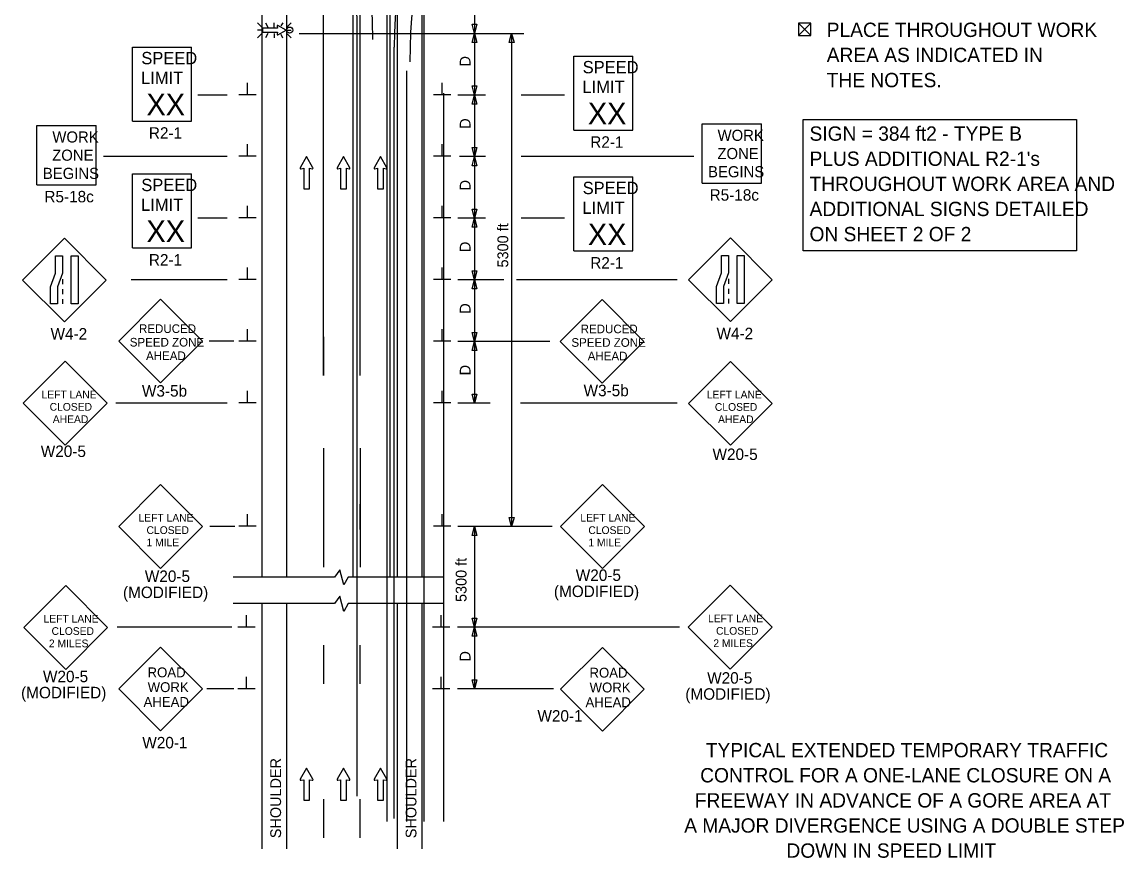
# Model space of a CAD drawing. Extents: x 16284 to 18474, y 5417 to 6974.
# Drawn here: x 16730 to 17445, y 5974 to 6516 of the extents above; entities that cross this region are included whole.
import ezdxf

# ---------------------------------------------------------------- set-up
doc = ezdxf.new("R2010")
doc.units = 0
for name, color, linetype in [('ALI_LEGAL_EX', 7, 'Continuous'), ('BORDER', 7, 'Continuous'), ('MT_SCRATCH_LEVEL_E', 7, 'Continuous'), ('PAVT_EDGE_EX', 7, 'Continuous'), ('TRAFFIC_SIGNS_PR', 7, 'Continuous'), ('TYPICAL_TEXT_DIMEN_EX', 7, 'Continuous'), ('TYPICAL_TEXT_DIMEN_PR', 7, 'Continuous')]:
    doc.layers.add(name, color=color, linetype=linetype)

msp = doc.modelspace()

# ---------------------------------------------------------------- linework, layer by layer
at = {"layer": 'ALI_LEGAL_EX'}
for p, q in [((16944.3, 6974.12), (16944.3, 6155.98)), ((16968.3, 6974.12), (16968.3, 6155.98)), ((16966.29, 6836.53), (16966.29, 5997.6)), ((16990.29, 6836.53), (16990.29, 5997.6)), ((16925.13, 6287.02), (16925.13, 6564.7)), ((16949.13, 6287.02), (16949.13, 6564.7)), ((16947.12, 6014.17), (16947.12, 6514.52)), ((16971.12, 5999.68), (16971.12, 6500.03)), ((16979.26, 5997.6), (16979.26, 6484.64)), ((17003.26, 5997.6), (17003.26, 6470.15)), ((16925.13, 6239.87), (16925.13, 6162.72)), ((16949.13, 6239.87), (16949.13, 6162.72))]:
    msp.add_line(p, q, dxfattribs=at)
for points in [[(16925.13, 6487.02), (16925.13, 6509.03)], [(16949.13, 6487.02), (16949.13, 6509.03)], [(16925.13, 6387.02), (16925.13, 6412.02)], [(16949.13, 6387.02), (16949.13, 6412.02)], [(16925.13, 6312.02), (16925.13, 6287.02)], [(16925.13, 6312.02), (16925.13, 6287.02)], [(16949.13, 6287.02), (16949.13, 6312.02)], [(16925.13, 6212.02), (16925.13, 6187.02)], [(16925.13, 6203.44), (16925.13, 6187.02)], [(16949.13, 6187.02), (16949.13, 6203.44)], [(16925.13, 6112.02), (16925.13, 6087.02)], [(16925.13, 6112.02), (16925.13, 6087.02)], [(16949.13, 6087.02), (16949.13, 6112.02)], [(16925.13, 6012.02), (16925.13, 5987.02)], [(16925.13, 6012.02), (16925.13, 5987.02)], [(16949.13, 5987.02), (16949.13, 6012.02)]]:
    msp.add_lwpolyline(points, dxfattribs=at)
for centre, radius, start, end in [((16583.12, 6514.52), 364, 0, 57.29578), ((16593.27, 6505.1), 364, 0, 57.29578), ((17311.12, 6500.03), 340, 129.56655, 180), ((17321.27, 6490.61), 340, 129.56655, 180)]:
    msp.add_arc(centre, radius, start, end, dxfattribs=at)
at = {"layer": 'MT_SCRATCH_LEVEL_E'}
for p, q in [((16914.27, 6429.09), (16910.15, 6421.85)), ((16918.41, 6421.85), (16914.27, 6429.09)), ((16938.17, 6429.09), (16934.06, 6421.85)), ((16942.32, 6421.85), (16938.17, 6429.09)), ((16962.22, 6429.09), (16958.11, 6421.85)), ((16966.37, 6421.85), (16962.22, 6429.09)), ((16910.64, 6421.16), (16912.41, 6421.48)), ((16912.41, 6421.48), (16912.41, 6408.22)), ((16916.16, 6408.22), (16916.16, 6421.48)), ((16916.16, 6421.48), (16917.93, 6421.16)), ((16934.54, 6421.16), (16936.32, 6421.48)), ((16936.32, 6421.48), (16936.32, 6408.22)), ((16940.06, 6408.22), (16940.06, 6421.48)), ((16940.06, 6421.48), (16941.84, 6421.16)), ((16958.59, 6421.16), (16960.37, 6421.48)), ((16960.37, 6421.48), (16960.37, 6408.22)), ((16964.11, 6408.22), (16964.11, 6421.48)), ((16964.11, 6421.48), (16965.89, 6421.16)), ((16912.41, 6408.22), (16916.16, 6408.22)), ((16936.32, 6408.22), (16940.06, 6408.22)), ((16960.37, 6408.22), (16964.11, 6408.22)), ((16914.27, 6032.27), (16910.15, 6025.03)), ((16918.41, 6025.03), (16914.27, 6032.27)), ((16938.17, 6032.27), (16934.06, 6025.03)), ((16942.32, 6025.03), (16938.17, 6032.27)), ((16962.22, 6032.27), (16958.11, 6025.03)), ((16966.37, 6025.03), (16962.22, 6032.27)), ((16910.64, 6024.34), (16912.41, 6024.65)), ((16912.41, 6024.65), (16912.41, 6011.4)), ((16916.16, 6011.4), (16916.16, 6024.65)), ((16916.16, 6024.65), (16917.93, 6024.34)), ((16934.54, 6024.34), (16936.32, 6024.65)), ((16936.32, 6024.65), (16936.32, 6011.4)), ((16940.06, 6011.4), (16940.06, 6024.65)), ((16940.06, 6024.65), (16941.84, 6024.34)), ((16958.59, 6024.34), (16960.37, 6024.65)), ((16960.37, 6024.65), (16960.37, 6011.4)), ((16964.11, 6011.4), (16964.11, 6024.65)), ((16964.11, 6024.65), (16965.89, 6024.34)), ((16912.41, 6011.4), (16916.16, 6011.4)), ((16936.32, 6011.4), (16940.06, 6011.4)), ((16960.37, 6011.4), (16964.11, 6011.4))]:
    msp.add_line(p, q, dxfattribs=at)
for centre, start, end in [((16910.56, 6421.62), 150.42484, 279.96381), ((16918, 6421.62), 260.03619, 29.77312), ((16934.47, 6421.62), 150.42484, 279.96381), ((16941.91, 6421.62), 260.03619, 29.77312), ((16958.52, 6421.62), 150.42484, 279.96381), ((16965.96, 6421.62), 260.03619, 29.77312), ((16910.56, 6024.8), 150.42484, 279.96381), ((16918, 6024.8), 260.03619, 29.77312), ((16934.47, 6024.8), 150.42484, 279.96381), ((16941.91, 6024.8), 260.03619, 29.77312), ((16958.52, 6024.8), 150.42484, 279.96381), ((16965.96, 6024.8), 260.03619, 29.77312)]:
    msp.add_arc(centre, 0.463, start, end, dxfattribs=at)
at = {"layer": 'PAVT_EDGE_EX'}
for p, q in [((16885.13, 6564.7), (16885.13, 6156.23)), ((16901.13, 6564.7), (16901.13, 6156.23)), ((16973.13, 6564.7), (16973.13, 6156.23)), ((16989.13, 6564.7), (16989.13, 6156.23)), ((16885.13, 6139.09), (16885.13, 5979.91)), ((16901.13, 6139.09), (16901.13, 5979.91)), ((16973.13, 6139.09), (16973.13, 5979.91)), ((16989.13, 6139.09), (16989.13, 5979.91))]:
    msp.add_line(p, q, dxfattribs=at)
at = {"layer": 'TRAFFIC_SIGNS_PR'}
for p, q in [((16885.2, 6513.11), (16882.38, 6515.93)), ((16887.5, 6515.93), (16889.13, 6513.11)), ((16893.29, 6513.11), (16893.29, 6515.93)), ((16898.76, 6515.93), (16897.55, 6513.83)), ((16904.19, 6515.92), (16901.37, 6513.11)), ((16885.2, 6511.07), (16882.38, 6511.07)), ((16885.2, 6509.04), (16882.38, 6506.22)), ((16889.15, 6509.04), (16887.52, 6506.22)), ((16893.29, 6509.04), (16893.29, 6506.22)), ((16901.37, 6511.07), (16904.19, 6511.07)), ((16904.19, 6506.22), (16901.37, 6509.04)), ((16897.47, 6508.41), (16898.73, 6506.22)), ((16801.22, 6500.11), (16839.62, 6500.11)), ((16801.22, 6452.11), (16801.22, 6500.11)), ((16839.62, 6452.11), (16839.62, 6500.11)), ((17087.7, 6494.24), (17126.1, 6494.24)), ((17087.7, 6446.24), (17087.7, 6494.24)), ((17126.1, 6446.24), (17126.1, 6494.24)), ((16801.22, 6452.11), (16839.62, 6452.11)), ((16739.26, 6410.82), (16739.26, 6449.22)), ((16739.26, 6449.22), (16777.66, 6449.22)), ((16777.66, 6410.82), (16777.66, 6449.22)), ((17087.7, 6446.24), (17126.1, 6446.24)), ((17171.03, 6411.89), (17171.03, 6450.29)), ((17171.03, 6450.29), (17209.43, 6450.29)), ((17209.43, 6411.89), (17209.43, 6450.29)), ((16801.22, 6417.81), (16839.62, 6417.81)), ((16801.22, 6369.81), (16801.22, 6417.81)), ((16839.62, 6369.81), (16839.62, 6417.81)), ((17087.7, 6415.85), (17126.1, 6415.85)), ((17087.7, 6367.85), (17087.7, 6415.85)), ((17126.1, 6367.85), (17126.1, 6415.85)), ((16739.26, 6410.82), (16777.66, 6410.82)), ((17171.03, 6411.89), (17209.43, 6411.89)), ((16757.12, 6376.12), (16729.97, 6348.97)), ((16784.27, 6348.97), (16757.12, 6376.12)), ((17189.39, 6376.32), (17162.24, 6349.17)), ((17216.54, 6349.17), (17189.39, 6376.32)), ((16801.22, 6369.81), (16839.62, 6369.81)), ((17087.7, 6367.85), (17126.1, 6367.85)), ((16729.97, 6348.97), (16757.12, 6321.81)), ((16755.87, 6349.46), (16755.87, 6346.26)), ((16757.12, 6321.81), (16784.27, 6348.97)), ((17162.24, 6349.17), (17189.39, 6322.02)), ((17188.14, 6349.66), (17188.14, 6346.46)), ((17189.39, 6322.02), (17216.54, 6349.17)), ((16755.87, 6343.06), (16755.87, 6339.86)), ((17188.14, 6343.26), (17188.14, 6340.06)), ((16755.87, 6336.66), (16755.87, 6333.46)), ((16819.44, 6336.46), (16792.29, 6309.31)), ((16846.59, 6309.31), (16819.44, 6336.46)), ((17106.11, 6336.29), (17078.95, 6309.14)), ((17133.26, 6309.14), (17106.11, 6336.29)), ((17188.14, 6336.86), (17188.14, 6333.66)), ((16792.29, 6309.31), (16819.44, 6282.16)), ((16819.44, 6282.16), (16846.59, 6309.31)), ((17078.95, 6309.14), (17106.11, 6281.98)), ((17106.11, 6281.98), (17133.26, 6309.14)), ((16757.55, 6296.22), (16730.36, 6269.03)), ((16784.74, 6269.03), (16757.55, 6296.22)), ((17189.35, 6296.15), (17162.17, 6268.96)), ((17216.54, 6268.96), (17189.35, 6296.15)), ((16730.36, 6269.03), (16757.55, 6241.85)), ((16757.55, 6241.85), (16784.74, 6269.03)), ((17162.17, 6268.96), (17189.35, 6241.78)), ((17189.35, 6241.78), (17216.54, 6268.96)), ((16819.54, 6216.22), (16792.35, 6189.04)), ((16846.73, 6189.04), (16819.54, 6216.22)), ((17106.33, 6216.21), (17079.14, 6189.02)), ((17133.51, 6189.02), (17106.33, 6216.21)), ((16792.35, 6189.04), (16819.54, 6161.85)), ((16819.54, 6161.85), (16846.73, 6189.04)), ((17079.14, 6189.02), (17106.33, 6161.83)), ((17106.33, 6161.83), (17133.51, 6189.02)), ((16757.91, 6150.73), (16730.73, 6123.54)), ((16785.1, 6123.54), (16757.91, 6150.73)), ((17189.21, 6150.88), (17162.02, 6123.69)), ((17216.39, 6123.69), (17189.21, 6150.88)), ((16730.73, 6123.54), (16757.91, 6096.35)), ((16757.91, 6096.35), (16785.1, 6123.54)), ((17162.02, 6123.69), (17189.21, 6096.51)), ((17189.21, 6096.51), (17216.39, 6123.69)), ((16819.47, 6110.81), (16792.32, 6083.66)), ((16846.63, 6083.66), (16819.47, 6110.81)), ((17106.31, 6110.61), (17079.15, 6083.45)), ((17133.46, 6083.45), (17106.31, 6110.61)), ((16792.32, 6083.66), (16819.47, 6056.51)), ((16819.47, 6056.51), (16846.63, 6083.66)), ((17079.15, 6083.45), (17106.31, 6056.3)), ((17106.31, 6056.3), (17133.46, 6083.45))]:
    msp.add_line(p, q, dxfattribs=at)
for points in [[(16895.11, 6513.76), (16895.34, 6512.46), (16885.62, 6512.46), (16885.62, 6509.72), (16895.34, 6509.72), (16895.11, 6508.41)], [(16895.61, 6508.06), (16900.92, 6511.07), (16895.61, 6514.11)]]:
    msp.add_lwpolyline(points, dxfattribs=at)
for points in [[(16755.87, 6364.7), (16755.87, 6353.52), (16752.53, 6344.64), (16752.53, 6333.46), (16748.04, 6333.46), (16748.04, 6344.64), (16751.38, 6353.52), (16751.38, 6364.7)], [(16766.01, 6364.7), (16766.01, 6333.46), (16761.52, 6333.46), (16761.52, 6364.7)], [(17188.14, 6364.91), (17188.14, 6353.73), (17184.8, 6344.84), (17184.8, 6333.66), (17180.31, 6333.66), (17180.31, 6344.84), (17183.65, 6353.73), (17183.65, 6364.91)], [(17198.28, 6364.91), (17198.28, 6333.66), (17193.79, 6333.66), (17193.79, 6364.91)]]:
    msp.add_lwpolyline(points, close=True, dxfattribs=at)
msp.add_circle((16903.24, 6511.12), 2, dxfattribs=at)
for centre, start, end in [((16895.45, 6513.81), 61.48329, 189.95933), ((16895.45, 6508.36), 170.73078, 298.89165)]:
    msp.add_arc(centre, 0.341, start, end, dxfattribs=at)
at = {"layer": 'TYPICAL_TEXT_DIMEN_EX'}
msp.add_lwpolyline([(17236.66, 6453.17), (17413.93, 6453.17), (17413.93, 6367.85), (17236.66, 6367.85)], close=True, dxfattribs=at)
at = {"layer": 'TYPICAL_TEXT_DIMEN_PR'}
for p, q in [((17023.24, 6541.14), (17023.24, 6509.03)), ((16909.53, 6509.03), (17055.35, 6509.03)), ((17023.24, 6509.03), (17021.67, 6514.9)), ((17021.67, 6514.9), (17023.24, 6514.9)), ((17021.67, 6503.17), (17023.24, 6509.03)), ((17023.24, 6514.9), (17024.81, 6514.9)), ((17024.81, 6514.9), (17023.24, 6509.03)), ((17023.24, 6509.03), (17023.24, 6469.03)), ((17023.24, 6509.03), (17024.81, 6503.17)), ((17045.77, 6503.17), (17047.34, 6509.03)), ((17047.34, 6509.03), (17047.34, 6189.03)), ((17047.34, 6509.03), (17048.91, 6503.17)), ((17233.46, 6515.74), (17241.46, 6507.74)), ((17233.46, 6507.74), (17241.46, 6515.74)), ((17023.24, 6503.17), (17021.67, 6503.17)), ((17024.81, 6503.17), (17023.24, 6503.17)), ((17047.34, 6503.17), (17045.77, 6503.17)), ((17048.91, 6503.17), (17047.34, 6503.17)), ((16876.01, 6469.12), (16876.01, 6476.9)), ((17002.26, 6469.12), (17002.26, 6476.9)), ((17023.24, 6469.03), (17021.67, 6474.9)), ((17021.67, 6474.9), (17023.24, 6474.9)), ((17023.24, 6474.9), (17024.81, 6474.9)), ((17024.81, 6474.9), (17023.24, 6469.03)), ((16862.74, 6469.03), (16843.67, 6469.03)), ((16881.63, 6469.12), (16870.38, 6469.12)), ((17007.88, 6469.12), (16996.63, 6469.12)), ((17030.45, 6469.03), (17012.41, 6469.03)), ((17021.67, 6463.17), (17023.24, 6469.03)), ((17023.24, 6469.03), (17023.24, 6429.03)), ((17023.24, 6469.03), (17024.81, 6463.17)), ((17081.63, 6469.03), (17053.57, 6469.03)), ((17023.24, 6463.17), (17021.67, 6463.17)), ((17024.81, 6463.17), (17023.24, 6463.17)), ((16875.89, 6429.28), (16875.89, 6437.06)), ((17002.26, 6429.28), (17002.26, 6437.06)), ((17023.24, 6429.03), (17021.67, 6434.9)), ((17021.67, 6434.9), (17023.24, 6434.9)), ((17023.24, 6434.9), (17024.81, 6434.9)), ((17024.81, 6434.9), (17023.24, 6429.03)), ((16862.74, 6429.03), (16782.5, 6429.03)), ((16881.52, 6429.28), (16870.27, 6429.28)), ((17007.88, 6429.28), (16996.63, 6429.28)), ((17030.45, 6429.03), (17013.53, 6429.03)), ((17021.67, 6423.17), (17023.24, 6429.03)), ((17023.24, 6423.17), (17021.67, 6423.17)), ((17023.24, 6429.03), (17023.24, 6389.03)), ((17023.24, 6429.03), (17024.81, 6423.17)), ((17024.81, 6423.17), (17023.24, 6423.17)), ((17165.52, 6429.03), (17053.57, 6429.03)), ((16875.89, 6389.28), (16875.89, 6397.06)), ((17002.26, 6389.28), (17002.26, 6397.06)), ((17023.24, 6389.03), (17021.67, 6394.9)), ((17021.67, 6394.9), (17023.24, 6394.9)), ((17023.24, 6394.9), (17024.81, 6394.9)), ((17024.81, 6394.9), (17023.24, 6389.03)), ((16862.74, 6389.03), (16843.67, 6389.03)), ((16881.52, 6389.28), (16870.27, 6389.28)), ((17007.88, 6389.28), (16996.63, 6389.28)), ((17030.45, 6389.03), (17012.41, 6389.03)), ((17021.67, 6383.17), (17023.24, 6389.03)), ((17023.24, 6389.03), (17023.24, 6349.03)), ((17023.24, 6389.03), (17024.81, 6383.17)), ((17081.63, 6389.03), (17053.57, 6389.03)), ((17023.24, 6383.17), (17021.67, 6383.17)), ((17024.81, 6383.17), (17023.24, 6383.17)), ((16875.89, 6349.28), (16875.89, 6357.06)), ((17002.26, 6349.28), (17002.26, 6357.06)), ((17023.24, 6349.03), (17021.67, 6354.9)), ((17021.67, 6354.9), (17023.24, 6354.9)), ((17023.24, 6354.9), (17024.81, 6354.9)), ((17024.81, 6354.9), (17023.24, 6349.03)), ((16862.74, 6349.03), (16800.38, 6349.03)), ((16881.52, 6349.28), (16870.27, 6349.28)), ((17007.88, 6349.28), (16996.63, 6349.28)), ((17042.25, 6349.03), (17012.41, 6349.03)), ((17021.67, 6343.17), (17023.24, 6349.03)), ((17023.24, 6349.03), (17023.24, 6309.03)), ((17023.24, 6349.03), (17024.81, 6343.17)), ((17154.85, 6349.03), (17050.57, 6349.03)), ((17023.24, 6343.17), (17021.67, 6343.17)), ((17024.81, 6343.17), (17023.24, 6343.17)), ((16875.89, 6309.28), (16875.89, 6317.06)), ((17002.26, 6309.28), (17002.26, 6317.06)), ((16867.07, 6309.28), (16850.99, 6309.28)), ((16881.52, 6309.28), (16870.27, 6309.28)), ((17007.88, 6309.28), (16996.63, 6309.28)), ((17072.18, 6309.03), (17012.41, 6309.03)), ((17023.24, 6309.03), (17021.67, 6314.9)), ((17021.67, 6314.9), (17023.24, 6314.9)), ((17021.67, 6303.17), (17023.24, 6309.03)), ((17023.24, 6314.9), (17024.81, 6314.9)), ((17024.81, 6314.9), (17023.24, 6309.03)), ((17023.24, 6309.03), (17023.24, 6269.03)), ((17023.24, 6309.03), (17024.81, 6303.17)), ((17023.24, 6303.17), (17021.67, 6303.17)), ((17024.81, 6303.17), (17023.24, 6303.17)), ((16875.89, 6269.28), (16875.89, 6277.06)), ((17002.26, 6269.28), (17002.26, 6277.06)), ((17023.24, 6269.03), (17021.67, 6274.9)), ((17021.67, 6274.9), (17023.24, 6274.9)), ((17023.24, 6274.9), (17024.81, 6274.9)), ((17024.81, 6274.9), (17023.24, 6269.03)), ((16862.74, 6269.03), (16790.51, 6269.03)), ((16881.52, 6269.28), (16870.27, 6269.28)), ((17007.88, 6269.28), (16996.63, 6269.28)), ((17033.44, 6269.03), (17012.41, 6269.03)), ((17154.85, 6269.03), (17053.17, 6269.03)), ((16875.89, 6189.28), (16875.89, 6197.06)), ((17002.26, 6189.28), (17002.26, 6197.06)), ((17047.34, 6189.03), (17045.77, 6194.9)), ((17045.77, 6194.9), (17047.34, 6194.9)), ((17047.34, 6194.9), (17048.91, 6194.9)), ((17048.91, 6194.9), (17047.34, 6189.03)), ((16867.75, 6189.03), (16851.39, 6189.03)), ((16881.52, 6189.28), (16870.27, 6189.28)), ((17007.88, 6189.28), (16996.63, 6189.28)), ((17073.63, 6189.03), (17012.41, 6189.03)), ((17021.67, 6183.17), (17023.24, 6189.03)), ((17023.24, 6189.03), (17023.24, 6123.69)), ((17023.24, 6189.03), (17024.81, 6183.17)), ((17023.24, 6183.17), (17021.67, 6183.17)), ((17024.81, 6183.17), (17023.24, 6183.17)), ((16935.74, 6161.03), (16932.48, 6156.23)), ((16938.48, 6151.09), (16935.74, 6161.03)), ((16932.48, 6156.23), (16866.54, 6156.23)), ((16941.22, 6156.23), (16938.48, 6151.09)), ((17003.55, 6156.23), (16941.22, 6156.23)), ((16935.74, 6143.89), (16932.48, 6139.09)), ((16938.48, 6133.95), (16935.74, 6143.89)), ((16932.48, 6139.09), (16866.54, 6139.09)), ((16941.22, 6139.09), (16938.48, 6133.95)), ((17003.55, 6139.09), (16941.22, 6139.09)), ((16875.34, 6123.69), (16875.34, 6131.48)), ((17001.51, 6123.69), (17001.51, 6131.48)), ((16865.72, 6123.69), (16791.34, 6123.69)), ((16880.96, 6123.69), (16869.71, 6123.69)), ((17007.13, 6123.69), (16995.88, 6123.69)), ((17156.38, 6123.69), (17012.13, 6123.69)), ((17023.24, 6123.69), (17021.67, 6129.56)), ((17021.67, 6129.56), (17023.24, 6129.56)), ((17021.67, 6117.83), (17023.24, 6123.69)), ((17023.24, 6129.56), (17024.81, 6129.56)), ((17024.81, 6129.56), (17023.24, 6123.69)), ((17023.24, 6123.69), (17023.24, 6083.69)), ((17023.24, 6123.69), (17024.81, 6117.83)), ((17023.24, 6117.83), (17021.67, 6117.83)), ((17024.81, 6117.83), (17023.24, 6117.83)), ((16875.34, 6083.69), (16875.34, 6091.48)), ((17001.51, 6083.69), (17001.51, 6091.48)), ((17023.24, 6083.69), (17021.67, 6089.56)), ((17021.67, 6089.56), (17023.24, 6089.56)), ((17023.24, 6089.56), (17024.81, 6089.56)), ((17024.81, 6089.56), (17023.24, 6083.69)), ((16866.99, 6083.69), (16849.51, 6083.69)), ((16880.96, 6083.69), (16869.71, 6083.69)), ((17007.13, 6083.69), (16995.88, 6083.69)), ((17074.45, 6083.69), (17012.13, 6083.69))]:
    msp.add_line(p, q, dxfattribs=at)
msp.add_lwpolyline([(17233.46, 6515.74), (17233.46, 6507.74), (17241.46, 6507.74), (17241.46, 6515.74)], close=True, dxfattribs=at)

# ---------------------------------------------------------------- texts
at = {"layer": 'BORDER'}
for s, p in [('TYPICAL EXTENDED TEMPORARY TRAFFIC', (17173.37, 6039.3)), ('CONTROL FOR A ONE-LANE CLOSURE ON A', (17169.74, 6023)), ('FREEWAY IN ADVANCE OF A GORE AREA AT', (17166.24, 6006.7)), ('A MAJOR DIVERGENCE USING A DOUBLE STEP', (17159.37, 5990.4)), ('DOWN IN SPEED LIMIT', (17225.74, 5974.11))]:
    msp.add_text(s, height=9.3, dxfattribs=at).set_placement(p)
at = {"layer": 'TRAFFIC_SIGNS_PR'}
for s, height, p in [('SPEED', 8, (16806.99, 6488.98)), ('SPEED', 8, (17093.47, 6483.1)), ('LIMIT', 8, (16806.83, 6476.18)), ('LIMIT', 8, (17093.31, 6470.3)), ('XX', 14.031, (16810.33, 6455.87)), ('XX', 14.031, (17096.82, 6450)), ('WORK', 7.217, (16749.26, 6438.19)), ('R2-1', 7.44, (16811.9, 6440.67)), ('WORK', 7.217, (17181.03, 6439.26)), ('R2-1', 7.44, (17098.38, 6434.8)), ('ZONE', 7.217, (16749.14, 6426.38)), ('ZONE', 7.217, (17180.91, 6427.45)), ('BEGINS', 7.217, (17174.84, 6415.64)), ('BEGINS', 7.217, (16743.07, 6414.57)), ('SPEED', 8, (16806.99, 6406.67)), ('SPEED', 8, (17093.47, 6404.71)), ('R5-18c', 7.44, (16744.07, 6399.38)), ('LIMIT', 8, (16806.83, 6393.87)), ('R5-18c', 7.44, (17175.84, 6400.45)), ('LIMIT', 8, (17093.31, 6391.91)), ('XX', 14.031, (16810.33, 6373.57)), ('XX', 14.031, (17096.82, 6371.61)), ('R2-1', 7.44, (16811.9, 6358.37)), ('R2-1', 7.44, (17098.38, 6356.41)), ('W4-2', 7.44, (16748.08, 6310.37)), ('REDUCED', 5.6, (16805.5, 6314.62)), ('REDUCED', 5.6, (17092.16, 6314.44)), ('W4-2', 7.44, (17180.35, 6310.58)), ('SPEED ZONE', 5.6, (16799.49, 6305.82)), ('SPEED ZONE', 5.6, (17086.16, 6305.64)), ('AHEAD', 5.6, (16810.05, 6297.02)), ('AHEAD', 5.6, (17096.72, 6296.84)), ('W3-5b', 7.44, (16807.4, 6273.32)), ('W3-5b', 7.44, (17094.06, 6273.58)), ('LEFT LANE', 5.006, (16742.23, 6272.19)), ('LEFT LANE', 5.006, (17174.04, 6272.12)), ('CLOSED', 5.006, (16747.47, 6264.19)), ('CLOSED', 5.006, (17179.27, 6264.11)), ('AHEAD', 5.006, (16749.53, 6256.18)), ('AHEAD', 5.006, (17181.33, 6256.1)), ('W20-5', 7.449, (16741.71, 6234.14)), ('W20-5', 7.449, (17177.73, 6232.19)), ('LEFT LANE', 5.006, (16805.15, 6192.19)), ('LEFT LANE', 5.006, (17091.94, 6192.18)), ('CLOSED', 5.006, (16810.36, 6184.19)), ('CLOSED', 5.006, (17097.15, 6184.17)), ('1 MILE', 5.006, (16810.36, 6176.18)), ('1 MILE', 5.006, (17097.15, 6176.16)), ('W20-5', 7.449, (16809.27, 6153.05)), ('W20-5', 7.449, (17088.98, 6153.73)), ('(MODIFIED)', 7.449, (17074.78, 6143.27)), ('(MODIFIED)', 7.449, (16795.08, 6142.6)), ('LEFT LANE', 5.006, (16743.52, 6126.69)), ('LEFT LANE', 5.006, (17174.82, 6126.85)), ('CLOSED', 5.006, (16748.74, 6118.69)), ('CLOSED', 5.006, (17180.03, 6118.84)), ('2 MILES', 5.006, (16746.99, 6110.68)), ('2 MILES', 5.006, (17178.28, 6110.83)), ('W20-5', 7.449, (16743.14, 6088.01)), ('ROAD', 6.4, (16811.02, 6091.19)), ('ROAD', 6.4, (17097.85, 6090.99)), ('W20-5', 7.449, (17174.27, 6087.07)), ('WORK', 6.4, (16811.12, 6081.6)), ('WORK', 6.4, (17097.96, 6081.39)), ('(MODIFIED)', 7.449, (16728.95, 6077.56)), ('(MODIFIED)', 7.449, (17160.08, 6076.62)), ('AHEAD', 6.4, (16808.43, 6071.99)), ('AHEAD', 6.4, (17095.27, 6071.79)), ('W20-1', 7.44, (17064.09, 6062.43)), ('W20-1', 7.44, (16807.64, 6045.07))]:
    msp.add_text(s, height=height, dxfattribs=at).set_placement(p)
at = {"layer": 'TYPICAL_TEXT_DIMEN_EX'}
for s, p in [('PLACE THROUGHOUT WORK', (17251.87, 6506.68)), ('AREA AS INDICATED IN', (17251.87, 6490.38)), ('THE NOTES.', (17251.87, 6474.08)), ('SIGN = 384 ft2 - TYPE B', (17240.71, 6439.34)), ("PLUS ADDITIONAL R2-1's", (17240.71, 6423.04)), ('THROUGHOUT WORK AREA AND', (17240.71, 6406.74)), ('ADDITIONAL SIGNS DETAILED', (17240.71, 6390.44)), ('ON SHEET 2 OF 2', (17240.71, 6374.14))]:
    msp.add_text(s, height=9.3, dxfattribs=at).set_placement(p)
at = {"layer": 'TYPICAL_TEXT_DIMEN_PR'}
for s, p in [('D', (17020.68, 6487.55)), ('D', (17020.68, 6447.12)), ('D', (17020.68, 6407.12)), ('5300 ft', (17045.14, 6357.12)), ('D', (17020.68, 6367.12)), ('D', (17020.68, 6327.12)), ('D', (17020.68, 6287.12)), ('5300 ft', (17018.06, 6140.07)), ('D', (17020.68, 6101.44)), ('SHOULDER', (16897.69, 5986.81)), ('SHOULDER', (16985.55, 5986.81))]:
    msp.add_text(s, height=7, rotation=90, dxfattribs=at).set_placement(p)

doc.saveas('drawing.dxf')
